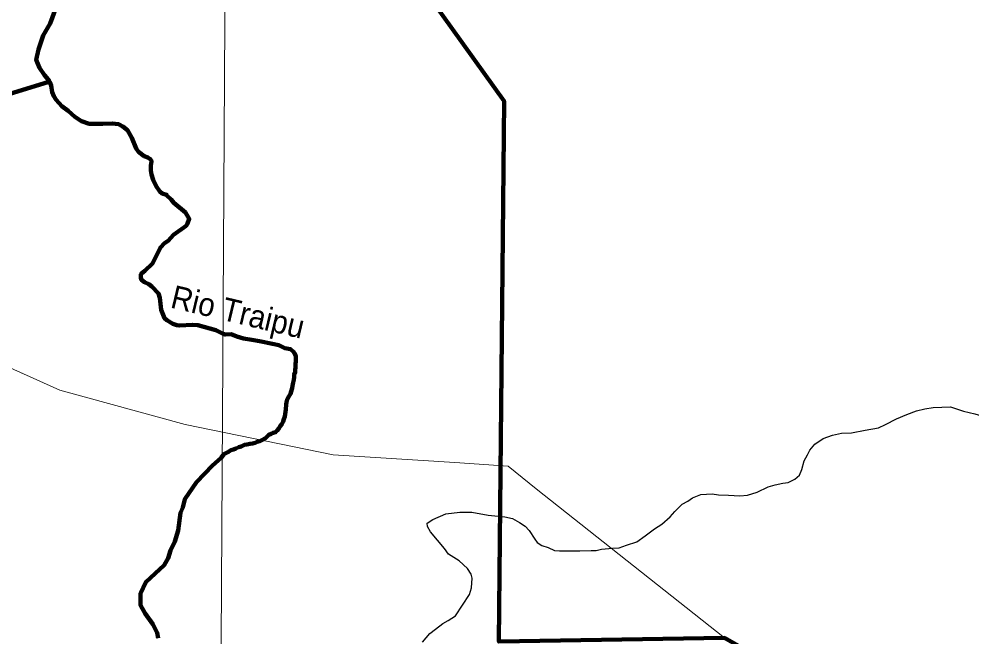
# Model space of a CAD drawing. Extents: x -1643653 to 4543381, y 1624270 to 13878484.
# Drawn here: x 714916 to 735516, y 8902999 to 8916368 of the extents above; entities that cross this region are included whole.
import ezdxf
from ezdxf.enums import TextEntityAlignment as Align

# ---------------------------------------------------------------- set-up
doc = ezdxf.new("R2010")
doc.units = 0
doc.header["$LTSCALE"] = 200
for name, color, linetype, lineweight in [('1', 7, 'Continuous', 13), ('12', 7, 'Continuous', 25), ('24', 7, 'Continuous', 25), ('53', 7, 'Continuous', 106), ('57', 7, 'Continuous', 13), ('58', 7, 'Continuous', 13), ('60', 7, 'Continuous', 13), ('9', 7, 'Continuous', 90)]:
    doc.layers.add(name, color=color, linetype=linetype, lineweight=lineweight)
doc.layers.add('49', color=7, linetype='Continuous')

msp = doc.modelspace()

# ---------------------------------------------------------------- linework, layer by layer
at = {"layer": '1'}
msp.add_lwpolyline([(719978.9, 9023574.5), (719561.6, 8949232.2), (719215.6, 8890710.6)], dxfattribs=at)
at = {"layer": '12'}
for points in [[(732698.6, 8907406), (732912.6, 8907415.8), (733208.3, 8907476.3), (733493.7, 8907526.8), (733646.8, 8907597.8), (733881.6, 8907714.5), (734106.1, 8907810.9), (734320.4, 8907892), (734498.8, 8907937.5), (734677.2, 8907962.7), (734865.7, 8907967.4), (735054.3, 8907977.3), (735334.1, 8907885.1), (735578.4, 8907823.5), (735863.4, 8907741.4), (736076.8, 8907598.4), (736483.7, 8907404.1), (736742.9, 8907255.9), (737103.6, 8906990.3), (737439.3, 8906842), (737612.3, 8906775.4), (737750.2, 8906727.3)], [(727039.6, 8904864.2), (727284.1, 8904868.9), (727391.1, 8904868.7), (727508.4, 8904899), (727747.9, 8904919), (727890.6, 8904928.9), (728048.7, 8904984.6), (728268, 8905055.5), (728451.9, 8905187.7), (728651.2, 8905340.1), (728809.4, 8905436.6), (728993.4, 8905594.2), (729095.8, 8905716.2), (729249.1, 8905868.8), (729371.7, 8905934.8), (729473.8, 8906011), (729657.5, 8906082), (729896.9, 8906091.7), (730039.5, 8906071.1), (730253.5, 8906065.6), (730497.9, 8906055), (730661, 8906064.9), (730870.1, 8906130.7), (731110, 8906247.4), (731263, 8906293), (731426.1, 8906328.3), (731543.3, 8906338.3), (731686.2, 8906409.4), (731788.5, 8906500.9), (731839.8, 8906623.1), (731891.5, 8906806.3), (731958.2, 8906938.7), (732014.6, 8907040.4), (732122.1, 8907172.7), (732300.8, 8907289.5), (732499.7, 8907365.6), (732698.6, 8907406)], [(723639.5, 8902883.8), (723793, 8903072), (723920.7, 8903168.5), (724079.1, 8903290.5), (724191.4, 8903356.5), (724349.7, 8903453), (724652, 8903916), (724698.3, 8904058.6), (724714.4, 8904272.5), (724689.2, 8904354.1), (724613.3, 8904481.5), (724430.5, 8904644.9), (724201.8, 8904787.9), (724110.5, 8904915.5), (723811.3, 8905272.6), (723745.5, 8905389.9), (723740.7, 8905461.2), (723858.1, 8905542.5), (724143.8, 8905659.1), (724444.6, 8905699.3), (724704.4, 8905698.9), (725060.7, 8905637.1), (725417.2, 8905595.7), (725585.2, 8905564.8), (725732.6, 8905477.9), (725859.7, 8905396.2), (725945.9, 8905304.3), (726062.4, 8905115.6), (726113.1, 8905039.1), (726219.8, 8904977.8), (726352.1, 8904931.7), (726489.4, 8904870.3), (726601.5, 8904865), (727039.6, 8904864.2)]]:
    msp.add_lwpolyline(points, dxfattribs=at)
at = {"layer": '24', "lineweight": 53}
for points in [[(715765.5, 8916761), (715585.2, 8916273.3), (715439.9, 8916014.5), (715332.6, 8915712.1), (715285.6, 8915483), (715360.4, 8915309.1), (715466.5, 8915151.7), (715544.8, 8915057.8), (715568.8, 8915033.9), (715582.8, 8914999.5)], [(715582.8, 8914999.5), (715607.3, 8914926.5), (715630.8, 8914782.1), (715664.2, 8914698.4), (715720.4, 8914621.3), (715841.4, 8914484.8), (715976.3, 8914382.9), (716121.9, 8914251.7), (716262.7, 8914158.2), (716430.6, 8914102.4), (716723.3, 8914098.2), (716931, 8914106.3), (717067.3, 8914089.8), (717160, 8914040), (717258.6, 8913960.8), (717350.2, 8913798.9), (717444.9, 8913569.6), (717500.7, 8913495.3), (717620.4, 8913403.7), (717696.9, 8913374.6), (717753.4, 8913338.3), (717771.3, 8913315.3), (717779.7, 8913284.7), (717767.4, 8913198.7), (717765.2, 8913088.6), (717776, 8913003.3), (717816.4, 8912891.5), (717881.6, 8912752), (717959.7, 8912633.8), (718012.2, 8912595.1), (718103.9, 8912566), (718108.4, 8912552.9), (718200.6, 8912462.7), (718263.8, 8912388), (718510.9, 8912180.7), (718595.9, 8912042.5), (718559.6, 8911942), (718525.1, 8911895.3), (718256.7, 8911695.7), (718139.8, 8911569.1), (718058.8, 8911518.2), (717971, 8911425.9), (717799.8, 8911079.5), (717637.2, 8910919.9), (717559.9, 8910863.9), (717548.7, 8910844.9), (717546.6, 8910765.8), (717564.2, 8910723.9), (717629.5, 8910673.2), (717717.9, 8910632.5), (717786.1, 8910583.9), (717932.5, 8910426.1), (717961.9, 8910338.5), (717987.1, 8910076.6), (718063.3, 8909892.7), (718110.2, 8909851.7), (718240.9, 8909774.5), (718323.8, 8909744.9), (718380.9, 8909735.3), (718665.9, 8909753.1), (718783.6, 8909747.4), (719169.5, 8909639.4), (719326.4, 8909556.3)], [(719326.4, 8909556.3), (719371.3, 8909542.5), (719371.3, 8909542.5), (719504.5, 8909548.1), (719504.5, 8909548.1), (719504.5, 8909548.1), (719626.5, 8909498.2)], [(719626.5, 8909498.2), (719765.2, 8909453.8), (719765.2, 8909453.8), (719765.2, 8909453.8), (719765.2, 8909453.8), (719948.4, 8909426.1), (719948.4, 8909426.1), (719948.4, 8909426.1), (720114.8, 8909398.4), (720114.8, 8909398.4), (720114.8, 8909398.4), (720392.3, 8909337.4), (720392.3, 8909337.4), (720392.3, 8909337.4), (720392.3, 8909337.4), (720531, 8909309.6), (720531, 8909309.6), (720531, 8909309.6), (720664.2, 8909248.6), (720780.7, 8909226.5), (720848.9, 8909167.8), (720879.1, 8909126.9), (720899.1, 8909075.8), (720898.7, 8909024.9), (720898.3, 8908963.8), (720892.8, 8908897.6), (720892.3, 8908831.3), (720886.9, 8908780.4), (720886.5, 8908724.4), (720865.8, 8908678.7), (720860.4, 8908622.7), (720854.9, 8908561.6), (720844.3, 8908500.6), (720828.6, 8908434.4), (720818, 8908383.6), (720797.2, 8908307.3), (720781.6, 8908256.4), (720750.7, 8908200.6), (720714.6, 8908139.7), (720699, 8908078.7), (720693.5, 8908027.8), (720680.1, 8907917.9)], [(720680.1, 8907917.9), (720671.8, 8907819.1), (720661.2, 8907768.2), (720640.5, 8907712.3), (720624.9, 8907661.5), (720594, 8907605.6), (720558.1, 8907560), (720532.3, 8907509.3), (720496.4, 8907468.7), (720460.5, 8907428.2), (720409.6, 8907413.3), (720363.7, 8907393.2), (720312.7, 8907373.1), (720276.8, 8907337.7), (720241, 8907302.3), (720179.7, 8907267), (720118.4, 8907231.8), (720062.3, 8907216.8), (720016.4, 8907196.8), (719965.5, 8907181.8), (719909.5, 8907177.1), (719843.3, 8907162.2), (719792.3, 8907152.3), (719720.9, 8907122.2), (719664.9, 8907107.3), (719603.6, 8907077.1), (719552.6, 8907057.1), (719496.6, 8907042.2), (719445.4, 8907001.8), (719343.4, 8906951.5), (719283.6, 8906877)], [(719283.6, 8906877), (719100.8, 8906711), (718751.9, 8906345.6), (718502.7, 8905980.3), (718452.8, 8905797.7), (718403, 8905681.4), (718353.1, 8905299.5), (718286.7, 8905067), (718187, 8904867.8), (718137.2, 8904701.7), (718054.1, 8904552.2), (717859.9, 8904374.3), (717854.7, 8904369.6)], [(717854.7, 8904369.6), (717655.3, 8904186.9), (717539, 8903937.8), (717539, 8903688.8), (717638.7, 8903506.1), (717804.9, 8903273.6), (717904.6, 8903091), (717921.2, 8902974.7)]]:
    msp.add_lwpolyline(points, dxfattribs=at)
at = {"layer": '53'}
for points in [[(715765.5, 8916761), (715585.2, 8916273.3), (715439.9, 8916014.5), (715332.6, 8915712.1), (715285.6, 8915483), (715360.4, 8915309.1), (715466.5, 8915151.7), (715544.8, 8915057.8), (715568.8, 8915033.9), (715582.8, 8914999.5)], [(715765.5, 8916761), (715585.2, 8916273.3), (715439.9, 8916014.5), (715332.6, 8915712.1), (715285.6, 8915483), (715360.4, 8915309.1), (715466.5, 8915151.7), (715544.8, 8915057.8), (715568.8, 8915033.9), (715582.8, 8914999.5)], [(715765.5, 8916761), (715585.2, 8916273.3), (715439.9, 8916014.5), (715332.6, 8915712.1), (715285.6, 8915483), (715360.4, 8915309.1), (715466.5, 8915151.7), (715544.8, 8915057.8), (715568.8, 8915033.9), (715582.8, 8914999.5)], [(715582.8, 8914999.5), (715607.3, 8914926.5), (715630.8, 8914782.1), (715664.2, 8914698.4), (715720.4, 8914621.3), (715841.4, 8914484.8), (715976.3, 8914382.9), (716121.9, 8914251.7), (716262.7, 8914158.2), (716430.6, 8914102.4), (716723.3, 8914098.2), (716931, 8914106.3), (717067.3, 8914089.8), (717160, 8914040), (717258.6, 8913960.8), (717350.2, 8913798.9), (717444.9, 8913569.6), (717500.7, 8913495.3), (717620.4, 8913403.7), (717696.9, 8913374.6), (717753.4, 8913338.3), (717771.3, 8913315.3), (717779.7, 8913284.7), (717767.4, 8913198.7), (717765.2, 8913088.6), (717776, 8913003.3), (717816.4, 8912891.5), (717881.6, 8912752), (717959.7, 8912633.8), (718012.2, 8912595.1), (718103.9, 8912566), (718108.4, 8912552.9), (718200.6, 8912462.7), (718263.8, 8912388), (718510.9, 8912180.7), (718595.9, 8912042.5), (718559.6, 8911942), (718525.1, 8911895.3), (718256.7, 8911695.7), (718139.8, 8911569.1), (718058.8, 8911518.2), (717971, 8911425.9), (717799.8, 8911079.5), (717637.2, 8910919.9), (717559.9, 8910863.9), (717548.7, 8910844.9), (717546.6, 8910765.8), (717564.2, 8910723.9), (717629.5, 8910673.2), (717717.9, 8910632.5), (717786.1, 8910583.9), (717932.5, 8910426.1), (717961.9, 8910338.5), (717987.1, 8910076.6), (718063.3, 8909892.7), (718110.2, 8909851.7), (718240.9, 8909774.5), (718323.8, 8909744.9), (718380.9, 8909735.3), (718665.9, 8909753.1), (718783.6, 8909747.4), (719169.5, 8909639.4), (719326.4, 8909556.3)], [(715582.8, 8914999.5), (715607.3, 8914926.5), (715630.8, 8914782.1), (715664.2, 8914698.4), (715720.4, 8914621.3), (715841.4, 8914484.8), (715976.3, 8914382.9), (716121.9, 8914251.7), (716262.7, 8914158.2), (716430.6, 8914102.4), (716723.3, 8914098.2), (716931, 8914106.3), (717067.3, 8914089.8), (717160, 8914040), (717258.6, 8913960.8), (717350.2, 8913798.9), (717444.9, 8913569.6), (717500.7, 8913495.3), (717620.4, 8913403.7), (717696.9, 8913374.6), (717753.4, 8913338.3), (717771.3, 8913315.3), (717779.7, 8913284.7), (717767.4, 8913198.7), (717765.2, 8913088.6), (717776, 8913003.3), (717816.4, 8912891.5), (717881.6, 8912752), (717959.7, 8912633.8), (718012.2, 8912595.1), (718103.9, 8912566), (718108.4, 8912552.9), (718200.6, 8912462.7), (718263.8, 8912388), (718510.9, 8912180.7), (718595.9, 8912042.5), (718559.6, 8911942), (718525.1, 8911895.3), (718256.7, 8911695.7), (718139.8, 8911569.1), (718058.8, 8911518.2), (717971, 8911425.9), (717799.8, 8911079.5), (717637.2, 8910919.9), (717559.9, 8910863.9), (717548.7, 8910844.9), (717546.6, 8910765.8), (717564.2, 8910723.9), (717629.5, 8910673.2), (717717.9, 8910632.5), (717786.1, 8910583.9), (717932.5, 8910426.1), (717961.9, 8910338.5), (717987.1, 8910076.6), (718063.3, 8909892.7), (718110.2, 8909851.7), (718240.9, 8909774.5), (718323.8, 8909744.9), (718380.9, 8909735.3), (718665.9, 8909753.1), (718783.6, 8909747.4), (719169.5, 8909639.4), (719326.4, 8909556.3)], [(715582.8, 8914999.5), (715607.3, 8914926.5), (715630.8, 8914782.1), (715664.2, 8914698.4), (715720.4, 8914621.3), (715841.4, 8914484.8), (715976.3, 8914382.9), (716121.9, 8914251.7), (716262.7, 8914158.2), (716430.6, 8914102.4), (716723.3, 8914098.2), (716931, 8914106.3), (717067.3, 8914089.8), (717160, 8914040), (717258.6, 8913960.8), (717350.2, 8913798.9), (717444.9, 8913569.6), (717500.7, 8913495.3), (717620.4, 8913403.7), (717696.9, 8913374.6), (717753.4, 8913338.3), (717771.3, 8913315.3), (717779.7, 8913284.7), (717767.4, 8913198.7), (717765.2, 8913088.6), (717776, 8913003.3), (717816.4, 8912891.5), (717881.6, 8912752), (717959.7, 8912633.8), (718012.2, 8912595.1), (718103.9, 8912566), (718108.4, 8912552.9), (718200.6, 8912462.7), (718263.8, 8912388), (718510.9, 8912180.7), (718595.9, 8912042.5), (718559.6, 8911942), (718525.1, 8911895.3), (718256.7, 8911695.7), (718139.8, 8911569.1), (718058.8, 8911518.2), (717971, 8911425.9), (717799.8, 8911079.5), (717637.2, 8910919.9), (717559.9, 8910863.9), (717548.7, 8910844.9), (717546.6, 8910765.8), (717564.2, 8910723.9), (717629.5, 8910673.2), (717717.9, 8910632.5), (717786.1, 8910583.9), (717932.5, 8910426.1), (717961.9, 8910338.5), (717987.1, 8910076.6), (718063.3, 8909892.7), (718110.2, 8909851.7), (718240.9, 8909774.5), (718323.8, 8909744.9), (718380.9, 8909735.3), (718665.9, 8909753.1), (718783.6, 8909747.4), (719169.5, 8909639.4), (719326.4, 8909556.3)], [(719326.4, 8909556.3), (719371.3, 8909542.5), (719371.3, 8909542.5), (719504.5, 8909548.1), (719504.5, 8909548.1), (719504.5, 8909548.1), (719626.5, 8909498.2)], [(719326.4, 8909556.3), (719371.3, 8909542.5), (719371.3, 8909542.5), (719504.5, 8909548.1), (719504.5, 8909548.1), (719504.5, 8909548.1), (719626.5, 8909498.2)], [(719326.4, 8909556.3), (719371.3, 8909542.5), (719371.3, 8909542.5), (719504.5, 8909548.1), (719504.5, 8909548.1), (719504.5, 8909548.1), (719626.5, 8909498.2)], [(719626.5, 8909498.2), (719765.2, 8909453.8), (719765.2, 8909453.8), (719765.2, 8909453.8), (719765.2, 8909453.8), (719948.4, 8909426.1), (719948.4, 8909426.1), (719948.4, 8909426.1), (720114.8, 8909398.4), (720114.8, 8909398.4), (720114.8, 8909398.4), (720392.3, 8909337.4), (720392.3, 8909337.4), (720392.3, 8909337.4), (720392.3, 8909337.4), (720531, 8909309.6), (720531, 8909309.6), (720531, 8909309.6), (720664.2, 8909248.6), (720780.7, 8909226.5), (720848.9, 8909167.8), (720879.1, 8909126.9), (720899.1, 8909075.8), (720898.7, 8909024.9), (720898.3, 8908963.8), (720892.8, 8908897.6), (720892.3, 8908831.3), (720886.9, 8908780.4), (720886.5, 8908724.4), (720865.8, 8908678.7), (720860.4, 8908622.7), (720854.9, 8908561.6), (720844.3, 8908500.6), (720828.6, 8908434.4), (720818, 8908383.6), (720797.2, 8908307.3), (720781.6, 8908256.4), (720750.7, 8908200.6), (720714.6, 8908139.7), (720699, 8908078.7), (720693.5, 8908027.8), (720680.1, 8907917.9)], [(719626.5, 8909498.2), (719765.2, 8909453.8), (719765.2, 8909453.8), (719765.2, 8909453.8), (719765.2, 8909453.8), (719948.4, 8909426.1), (719948.4, 8909426.1), (719948.4, 8909426.1), (720114.8, 8909398.4), (720114.8, 8909398.4), (720114.8, 8909398.4), (720392.3, 8909337.4), (720392.3, 8909337.4), (720392.3, 8909337.4), (720392.3, 8909337.4), (720531, 8909309.6), (720531, 8909309.6), (720531, 8909309.6), (720664.2, 8909248.6), (720780.7, 8909226.5), (720848.9, 8909167.8), (720879.1, 8909126.9), (720899.1, 8909075.8), (720898.7, 8909024.9), (720898.3, 8908963.8), (720892.8, 8908897.6), (720892.3, 8908831.3), (720886.9, 8908780.4), (720886.5, 8908724.4), (720865.8, 8908678.7), (720860.4, 8908622.7), (720854.9, 8908561.6), (720844.3, 8908500.6), (720828.6, 8908434.4), (720818, 8908383.6), (720797.2, 8908307.3), (720781.6, 8908256.4), (720750.7, 8908200.6), (720714.6, 8908139.7), (720699, 8908078.7), (720693.5, 8908027.8), (720680.1, 8907917.9)], [(719626.5, 8909498.2), (719765.2, 8909453.8), (719765.2, 8909453.8), (719765.2, 8909453.8), (719765.2, 8909453.8), (719948.4, 8909426.1), (719948.4, 8909426.1), (719948.4, 8909426.1), (720114.8, 8909398.4), (720114.8, 8909398.4), (720114.8, 8909398.4), (720392.3, 8909337.4), (720392.3, 8909337.4), (720392.3, 8909337.4), (720392.3, 8909337.4), (720531, 8909309.6), (720531, 8909309.6), (720531, 8909309.6), (720664.2, 8909248.6), (720780.7, 8909226.5), (720848.9, 8909167.8), (720879.1, 8909126.9), (720899.1, 8909075.8), (720898.7, 8909024.9), (720898.3, 8908963.8), (720892.8, 8908897.6), (720892.3, 8908831.3), (720886.9, 8908780.4), (720886.5, 8908724.4), (720865.8, 8908678.7), (720860.4, 8908622.7), (720854.9, 8908561.6), (720844.3, 8908500.6), (720828.6, 8908434.4), (720818, 8908383.6), (720797.2, 8908307.3), (720781.6, 8908256.4), (720750.7, 8908200.6), (720714.6, 8908139.7), (720699, 8908078.7), (720693.5, 8908027.8), (720680.1, 8907917.9)], [(720680.1, 8907917.9), (720671.8, 8907819.1), (720661.2, 8907768.2), (720640.5, 8907712.3), (720624.9, 8907661.5), (720594, 8907605.6), (720558.1, 8907560), (720532.3, 8907509.3), (720496.4, 8907468.7), (720460.5, 8907428.2), (720409.6, 8907413.3), (720363.7, 8907393.2), (720312.7, 8907373.1), (720276.8, 8907337.7), (720241, 8907302.3), (720179.7, 8907267), (720118.4, 8907231.8), (720062.3, 8907216.8), (720016.4, 8907196.8), (719965.5, 8907181.8), (719909.5, 8907177.1), (719843.3, 8907162.2), (719792.3, 8907152.3), (719720.9, 8907122.2), (719664.9, 8907107.3), (719603.6, 8907077.1), (719552.6, 8907057.1), (719496.6, 8907042.2), (719445.4, 8907001.8), (719343.4, 8906951.5), (719283.6, 8906877)], [(720680.1, 8907917.9), (720671.8, 8907819.1), (720661.2, 8907768.2), (720640.5, 8907712.3), (720624.9, 8907661.5), (720594, 8907605.6), (720558.1, 8907560), (720532.3, 8907509.3), (720496.4, 8907468.7), (720460.5, 8907428.2), (720409.6, 8907413.3), (720363.7, 8907393.2), (720312.7, 8907373.1), (720276.8, 8907337.7), (720241, 8907302.3), (720179.7, 8907267), (720118.4, 8907231.8), (720062.3, 8907216.8), (720016.4, 8907196.8), (719965.5, 8907181.8), (719909.5, 8907177.1), (719843.3, 8907162.2), (719792.3, 8907152.3), (719720.9, 8907122.2), (719664.9, 8907107.3), (719603.6, 8907077.1), (719552.6, 8907057.1), (719496.6, 8907042.2), (719445.4, 8907001.8), (719343.4, 8906951.5), (719283.6, 8906877)], [(720680.1, 8907917.9), (720671.8, 8907819.1), (720661.2, 8907768.2), (720640.5, 8907712.3), (720624.9, 8907661.5), (720594, 8907605.6), (720558.1, 8907560), (720532.3, 8907509.3), (720496.4, 8907468.7), (720460.5, 8907428.2), (720409.6, 8907413.3), (720363.7, 8907393.2), (720312.7, 8907373.1), (720276.8, 8907337.7), (720241, 8907302.3), (720179.7, 8907267), (720118.4, 8907231.8), (720062.3, 8907216.8), (720016.4, 8907196.8), (719965.5, 8907181.8), (719909.5, 8907177.1), (719843.3, 8907162.2), (719792.3, 8907152.3), (719720.9, 8907122.2), (719664.9, 8907107.3), (719603.6, 8907077.1), (719552.6, 8907057.1), (719496.6, 8907042.2), (719445.4, 8907001.8), (719343.4, 8906951.5), (719283.6, 8906877)], [(719283.6, 8906877), (719100.8, 8906711), (718751.9, 8906345.6), (718502.7, 8905980.3), (718452.8, 8905797.7), (718403, 8905681.4), (718353.1, 8905299.5), (718286.7, 8905067), (718187, 8904867.8), (718137.2, 8904701.7), (718054.1, 8904552.2), (717859.9, 8904374.3), (717854.7, 8904369.6)], [(719283.6, 8906877), (719100.8, 8906711), (718751.9, 8906345.6), (718502.7, 8905980.3), (718452.8, 8905797.7), (718403, 8905681.4), (718353.1, 8905299.5), (718286.7, 8905067), (718187, 8904867.8), (718137.2, 8904701.7), (718054.1, 8904552.2), (717859.9, 8904374.3), (717854.7, 8904369.6)], [(719283.6, 8906877), (719100.8, 8906711), (718751.9, 8906345.6), (718502.7, 8905980.3), (718452.8, 8905797.7), (718403, 8905681.4), (718353.1, 8905299.5), (718286.7, 8905067), (718187, 8904867.8), (718137.2, 8904701.7), (718054.1, 8904552.2), (717859.9, 8904374.3), (717854.7, 8904369.6)], [(717854.7, 8904369.6), (717655.3, 8904186.9), (717539, 8903937.8), (717539, 8903688.8), (717638.7, 8903506.1), (717804.9, 8903273.6), (717904.6, 8903091), (717921.2, 8902974.7)], [(717854.7, 8904369.6), (717655.3, 8904186.9), (717539, 8903937.8), (717539, 8903688.8), (717638.7, 8903506.1), (717804.9, 8903273.6), (717904.6, 8903091), (717921.2, 8902974.7)], [(717854.7, 8904369.6), (717655.3, 8904186.9), (717539, 8903937.8), (717539, 8903688.8), (717638.7, 8903506.1), (717804.9, 8903273.6), (717904.6, 8903091), (717921.2, 8902974.7)]]:
    msp.add_lwpolyline(points, dxfattribs=at)
at = {"layer": '57'}
for points in [[(714150.8, 8909075.2), (715793.9, 8908335.5), (718505, 8907595.7), (721708.9, 8906938.1), (724337.8, 8906773.8), (725488, 8906691.6), (726092.5, 8906203.6), (730163.4, 8902976.8), (733469.4, 8901085.6), (736775.3, 8899194.4), (741371.9, 8898310.2), (741034.6, 8900357.7)], [(741034.6, 8900357.7), (741371.9, 8898310.2), (736775.3, 8899194.4), (733469.4, 8901085.6), (730163.4, 8902976.8), (726092.5, 8906203.6), (725488, 8906691.6), (724337.8, 8906773.8), (721708.9, 8906938.1), (718505, 8907595.7), (715793.9, 8908335.5), (714150.8, 8909075.2)]]:
    msp.add_lwpolyline(points, dxfattribs=at)
at = {"layer": '58'}
msp.add_lwpolyline([(714150.8, 8909075.2), (715793.9, 8908335.5), (718505, 8907595.7), (721708.9, 8906938.1), (724337.8, 8906773.8), (725488, 8906691.6), (726092.5, 8906203.6), (730163.4, 8902976.8), (733469.4, 8901085.6), (736775.3, 8899194.4), (741371.9, 8898310.2), (741034.6, 8900357.7)], dxfattribs=at)
at = {"layer": '60', "lineweight": 25}
msp.add_spline([(814781, 9009175.5), (814787.2, 9009173.4), (814796.9, 9009173.4), (814799.4, 9009172.4), (814805.1, 9009174.5), (814805.6, 9009176.5), (814811.7, 9009179.5), (814811.7, 9009179.5), (814801.5, 9009181), (814790.7, 9009181.5), (814784.1, 9009183.1), (814777.4, 9009185.1), (814778.4, 9009175.5)], degree=3, dxfattribs=at)
at = {"layer": '9'}
msp.add_line((710134.6, 8913345.1), (715561.4, 8915010.8), dxfattribs=at)
for points in [[(741371.9, 8898310.2), (736775.3, 8899194.4), (730163.4, 8902976.8), (725291.2, 8902898), (725401.2, 8914588.3), (719613.1, 8922670.1)], [(715765.5, 8916761), (715585.2, 8916273.3), (715439.9, 8916014.5), (715332.6, 8915712.1), (715285.6, 8915483), (715360.4, 8915309.1), (715466.5, 8915151.7), (715544.8, 8915057.8), (715568.8, 8915033.9), (715582.8, 8914999.5), (715585.3, 8914991.8)], [(715765.5, 8916761), (715585.2, 8916273.3), (715439.9, 8916014.5), (715332.6, 8915712.1), (715285.6, 8915483), (715360.4, 8915309.1), (715466.5, 8915151.7), (715544.8, 8915057.8), (715568.8, 8915033.9), (715582.8, 8914999.5), (715585.3, 8914991.8)]]:
    msp.add_lwpolyline(points, dxfattribs=at)

# ---------------------------------------------------------------- texts
at = {"layer": '49', "width": 0.95}
msp.add_text('Rio Traipu', height=500, rotation=346.601, dxfattribs=at).set_placement((719591, 8909789.6), align=Align.CENTER)

doc.saveas('drawing.dxf')
